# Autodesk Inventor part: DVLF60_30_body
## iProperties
Created: 2010-03
Part Number: DVLF60_30_body
Document SubType Name: Modeling
Designer: TB
Mass: 737.882 g
Surface Area: 1331.22 cm^2
Volume: 737.882 cm^3
Density: 1 g/cm^3
Author: TB
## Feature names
1. Kropp [Revolution]
2. Chamfer
3. Extrusion2
4. Hole1
5. Revolution2
6. Hole2
7. Fillet1
8. Extrusion3
9. Hole3
